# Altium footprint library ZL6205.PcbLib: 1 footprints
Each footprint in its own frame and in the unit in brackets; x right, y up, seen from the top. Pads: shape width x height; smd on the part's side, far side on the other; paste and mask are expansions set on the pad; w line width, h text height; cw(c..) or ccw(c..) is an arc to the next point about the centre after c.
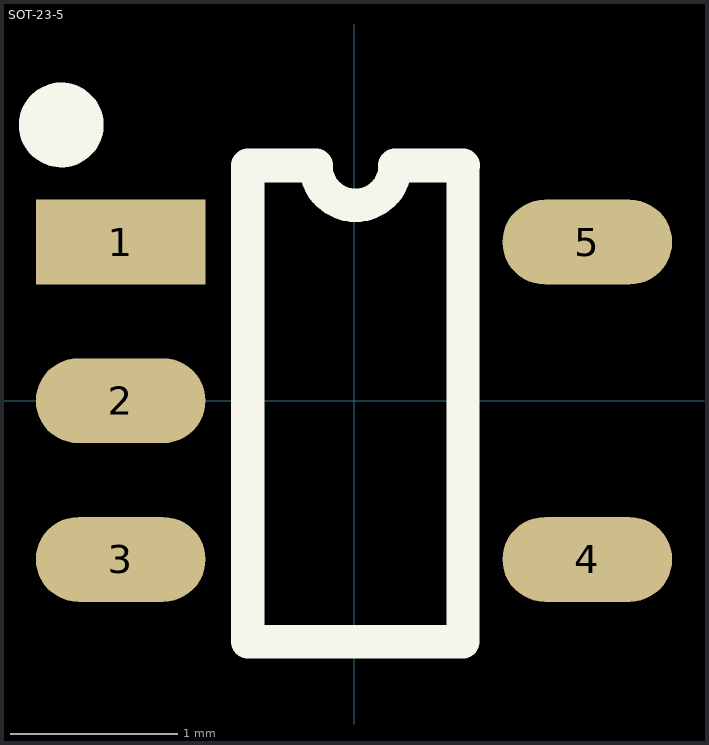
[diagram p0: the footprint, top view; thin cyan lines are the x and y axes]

## SOT-23-5 [mil]
pads (5):
  rect 40x20 smd: 1(-55,37.4)
  oval 40x20 smd: 2(-55,0) 3(-55,-37.4) 4(55,-37.4) 5(55,37.4)
Top Overlay:
  circle w10: c-69,65 r5
  lines w7.87: -25,55.4 -25,-56.8 25.7,-56.8 25.7,55.4 ; -9,55.4 ccw(c0.35,55.4) 9.7,55.4
  lines w8: -25,55.4 -9,55.4 ; 9.7,55.4 25.7,55.4
3D body: height 42.79, standoff -0.51, extent -55.16,-57.06 55.09,57.09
